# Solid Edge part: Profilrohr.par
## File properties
Username: bmolnar
Dokumentum tartalom típus: 0
Author: bmolnar
Last saved by: bmolnar
Revision: 91
Sűrűség: 0,000 kg/m^3
Pontosság: 0,990
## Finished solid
Body 1: solid body, 115 faces, 338 edges, 224 vertices.
  Faces by surface: cylinder 59, plane 56
  Edges by curve: line 220, circle 118
Bounding box of the edges (mm): 77.000 x 77.000 x 181.500, from (-38.5, -38.5, -5) to (38.5, 38.5, 176.5).
Cylindrical faces by radius (mm): R0.15 x24, R0.25 x24, R1 x4, R12 x4, R13.5 x2, R31.5 x1
Planar faces by outward normal: +x 13, +y 14, +z 1, -x 13, -y 14, -z 1
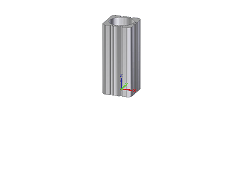
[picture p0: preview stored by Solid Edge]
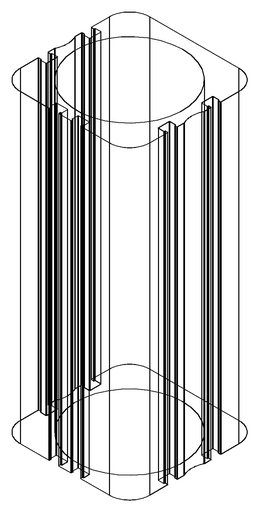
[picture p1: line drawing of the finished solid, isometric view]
